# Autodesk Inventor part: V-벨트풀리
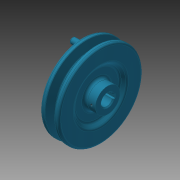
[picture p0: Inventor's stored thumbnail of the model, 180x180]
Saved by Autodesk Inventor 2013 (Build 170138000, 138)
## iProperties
Company: 한국ATC센터
Created: 2015-12
Part Number: V-벨트풀리
Document SubType Name: Modeling
Designer: mdu
Density: 7.25 g/cm^3
Mass: 596.622 g
Surface Area: 212.232 cm^2
Volume: 82.2926 cm^3
Material: 주철
Author: mdu
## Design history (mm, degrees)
sketch "스케치1"
  geometry: L1 (-13, 0)-(13, 0); L2 (-13, 0)-(-13, 12.5); L3 (-13, 12.5)-(-9, 12.5); L4 (-9, 12.5)-(-9, 23); L5 (-9, 23)-(-13, 27); L6 (-13, 27)-(-13, 42.7); L7 (-13, 42.7)-(-8.325, 42.7); L8 (-8.325, 42.7)-(-5.574, 33.7); L9 (-5.574, 33.7)-(-1.426, 33.7); L10 (-1.426, 33.7)-(1.325, 42.7); L11 (1.325, 42.7)-(6, 42.7); L12 (6, 42.7)-(6, 27); L13 (6, 27)-(2, 23); L14 (2, 23)-(2, 12.5); L15 (2, 12.5)-(13, 12.5); L16 (13, 12.5)-(13, 0); L17 (-7.5, 40)-(0.5, 40); 2 further points
  constraints: 34 end point, 6 parallel, 5 collinear, 5 equal length, 4 perpendicular, 2 point on line, 1 coincident, 1 horizontal, 1 midpoint
  dimensions: "d0" = 26 distance of L1.start L1.end; "d1" = 2.7 distance between parallel lines of L7 L17; "d2" = 6.3 distance between parallel lines of L9 L17; "d3" = 8 distance of L17.start L17.end; "d4" = 34 deg angle of L10 L8; "d5" = 19 distance between parallel lines of L12 L6; "d7" = 25 diameter of L15 L1; "d8" = 46 diameter of L13.end L1; "d9" = 54 diameter of L12.end L1; "d10" = 4 distance between parallel lines of L2 L4; "d11" = 80 diameter of L17 L1
revolve "회전1" sketch "스케치1" stored, may be unused: angle "d12" = 90 deg
sketch "스케치2"
  geometry: L1 (-2, 5.657)-(-2, 7.8); L2 (-2, 7.8)-(2, 7.8); L3 (2, 7.8)-(2, 5.657); A1 r 6 centre (0, 0) between (-2, 5.657) and (2, 5.657); 1 further point
  constraints: 6 end point, 2 parallel, 2 point on circle, 1 centre point, 1 coincident, 1 perpendicular, 1 vertical
  dimensions: "d13" = 12 diameter of A1; "d14" = 13.8 dimension on A1 L2; "d15" = 4 distance of L1.end L2.end
extrude "돌출1" cut sketch "스케치2" stored distance "d16" = 10; taper "d17" = 0 deg
node "작업 평면1"
sketch "스케치3"
  geometry: L1 (-5.5, 12.5)-(-5.5, -12.5) reference; L2 (20.5, 27)-(20.5, -27) reference; 3 further points
  constraints: 1 horizontal alignment, 1 midpoint
  dimensions: "d18" = 4 distance from line of point (-1.5, 0) L1; "d33" = 22 distance from line of point (-1.5, 0) L2 (derived)
hole "구멍1" sketch "스케치3" at (-1.5, 0) diameter "d19" = 2.459; stored, may be unused: countersink angle "d23" = 90 deg, drill point angle "d25" = 118 deg; dims "d20" = 6, "d21" = 4, "d22" = 2, "d24" = 8
fillet "모깎기1" dims "d26" = 2, "d27" = 0.5, "d28" = 1, "d29" = 3
chamfer "모따기1" distance "d30" = 1; stored, may be unused: second distance "d31" = 2, angle "d32" = 45 deg
sketch "스케치4" dims "d35" = 70
  geometry: C1 r 3 at (35, 0); 2 further points
  constraints: 2 horizontal alignment, 1 centre point, 1 coincident, 2 other
  dimensions: "d34" = 6 diameter of C1
extrude "돌출2" join sketch "스케치4" distance "d36" = 10; taper "d37" = 0 deg
fillet "모깎기2" dims "d38" = 0.5, "d39" = 1
node "솔리드1"
